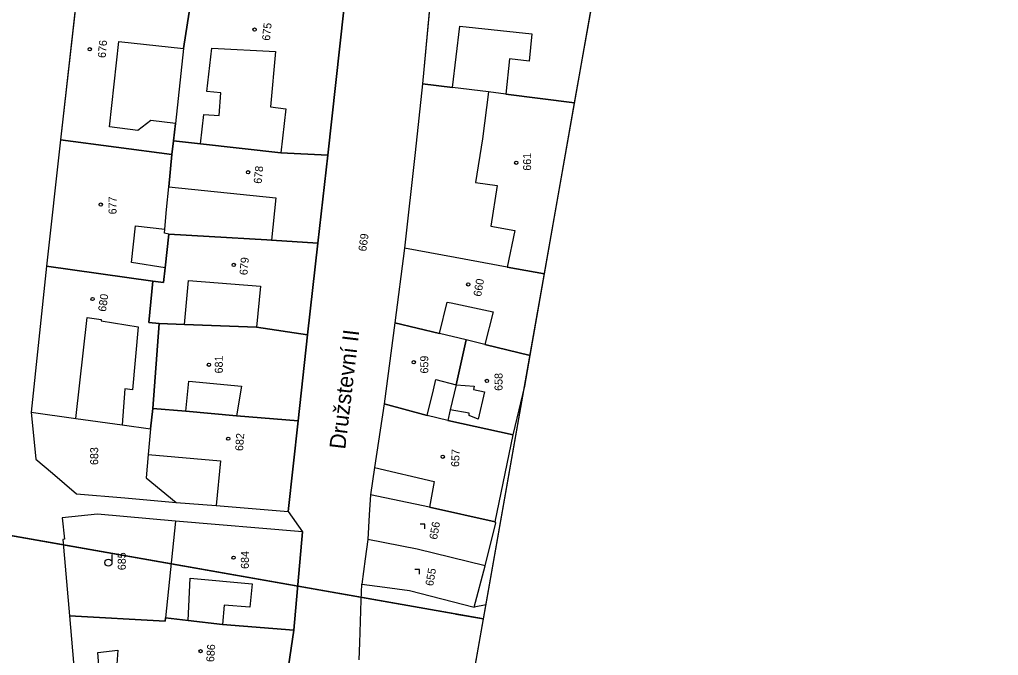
# Model space of a CAD drawing. Extents: x -534481 to -534256, y -1190577 to -1190138.
# Drawn here: x -534365.7 to -534261.7, y -1190477.6 to -1190410 of the extents above; entities that cross this region are included whole.
import ezdxf

# ---------------------------------------------------------------- set-up
doc = ezdxf.new("R2010")
doc.units = 0
for name, color, linetype in [('_rámeček', 7, 'Continuous'), ('_rámeček_mřížka', 7, 'Continuous'), ('Hranice parcel', 7, 'Continuous'), ('Parcelní čísla', 7, 'Continuous'), ('Polygon budovy', 7, 'Continuous'), ('Pop  PČ popisy', 7, 'Continuous'), ('Značky budov', 7, 'Continuous'), ('Značky kultur', 7, 'Continuous')]:
    doc.layers.add(name, color=color, linetype=linetype)

msp = doc.modelspace()

# ---------------------------------------------------------------- linework, layer by layer
at = {"layer": '_rámeček'}
for q in [(-534298.13, -1190370.27), (-534462.61, -1190447.89)]:
    msp.add_line((-534316.37, -1190473.68), q, dxfattribs=at)
for points in [[(-534407.91, -1190137.67), (-534480.84, -1190551.29), (-534334.6, -1190577.08), (-534261.67, -1190163.46)], [(-534298.13, -1190370.27), (-534444.38, -1190344.48), (-534462.61, -1190447.89), (-534316.37, -1190473.68)], [(-534480.84, -1190551.29), (-534334.6, -1190577.08), (-534316.37, -1190473.68)]]:
    msp.add_lwpolyline(points, dxfattribs=at)
at = {"layer": '_rámeček_mřížka'}
msp.add_line((-534319.32, -1190473.15), (-534316.37, -1190473.68), dxfattribs=at)
msp.add_lwpolyline([(-534480.84, -1190551.29), (-534334.6, -1190577.08), (-534261.67, -1190163.46)], dxfattribs=at)
at = {"layer": 'Hranice parcel'}
for p, q in [((-534321.81, -1190405.38), (-534322.86, -1190416.77)), ((-534359.48, -1190406.45), (-534361.32, -1190422.75)), ((-534331.23, -1190408.93), (-534332.91, -1190424.36)), ((-534361.32, -1190422.75), (-534362.8, -1190436.16)), ((-534361.32, -1190422.75), (-534349.49, -1190424.31)), ((-534349.49, -1190424.31), (-534349.31, -1190422.85)), ((-534332.91, -1190424.36), (-534333.96, -1190433.74)), ((-534333.96, -1190433.74), (-534335.08, -1190443.48)), ((-534324.75, -1190434.26), (-534325.81, -1190442.2)), ((-534362.8, -1190436.16), (-534364.44, -1190451.69)), ((-534362.8, -1190436.16), (-534351.49, -1190437.77)), ((-534351.49, -1190451.29), (-534350.82, -1190442.28)), ((-534325.81, -1190442.2), (-534326.91, -1190450.79)), ((-534335.08, -1190443.48), (-534336.06, -1190452.6)), ((-534313.23, -1190454.11), (-534312, -1190448.93)), ((-534351.77, -1190453.45), (-534351.49, -1190451.29)), ((-534336.06, -1190452.6), (-534337.13, -1190462.26)), ((-534313.23, -1190454.11), (-534320.15, -1190452.59)), ((-534351.77, -1190453.45), (-534351.99, -1190456.19)), ((-534315.15, -1190463.36), (-534313.23, -1190454.11)), ((-534337.13, -1190462.26), (-534335.61, -1190464.4)), ((-534349.11, -1190463.29), (-534350.15, -1190473.56)), ((-534335.61, -1190464.4), (-534349.11, -1190463.29)), ((-534335.61, -1190464.4), (-534336.54, -1190474.87)), ((-534317.36, -1190472.42), (-534316.19, -1190468.02)), ((-534360.35, -1190473.34), (-534359.92, -1190478.31))]:
    msp.add_line(p, q, dxfattribs=at)
for points in [[(-534347.45, -1190408.02), (-534348.24, -1190413.03), (-534349.11, -1190420.99), (-534349.31, -1190422.85)], [(-534322.86, -1190416.77), (-534323.65, -1190424.09), (-534324.75, -1190434.26)], [(-534306.7, -1190418.82), (-534314.01, -1190417.87), (-534315.84, -1190417.64), (-534319.66, -1190417.17), (-534322.86, -1190416.77)], [(-534349.31, -1190422.85), (-534346.43, -1190423.17), (-534337.91, -1190424.11), (-534332.91, -1190424.36)], [(-534349.79, -1190432.77), (-534350.28, -1190432.67), (-534350.24, -1190432.22), (-534350.04, -1190430.15), (-534349.82, -1190427.74), (-534349.49, -1190424.31)], [(-534351.49, -1190437.77), (-534350.38, -1190437.91), (-534350.2, -1190436.34), (-534349.79, -1190432.77)], [(-534349.79, -1190432.77), (-534345.53, -1190433.02), (-534339.38, -1190433.37), (-534338.88, -1190433.41), (-534333.96, -1190433.74)], [(-534309.9, -1190437), (-534313.86, -1190436.27), (-534319.38, -1190435.25), (-534324.75, -1190434.26)], [(-534351.49, -1190437.77), (-534351.94, -1190442.14), (-534350.82, -1190442.28)], [(-534350.82, -1190442.28), (-534348.14, -1190442.37), (-534340.49, -1190442.65), (-534335.08, -1190443.48)], [(-534318.21, -1190444.01), (-534321.04, -1190443.31), (-534325.81, -1190442.2)], [(-534318.21, -1190444.01), (-534319.29, -1190448.78), (-534319.9, -1190451.46), (-534320.15, -1190452.59)], [(-534311.43, -1190445.66), (-534316.23, -1190444.51), (-534318.21, -1190444.01)], [(-534326.91, -1190450.79), (-534327.94, -1190457.58), (-534328.38, -1190460.47)], [(-534320.15, -1190452.59), (-534322.37, -1190452.05), (-534326.91, -1190450.79)], [(-534364.44, -1190451.69), (-534363.92, -1190456.68), (-534362.18, -1190458.17), (-534359.62, -1190460.37), (-534354.49, -1190460.81), (-534349.01, -1190461.28)], [(-534364.44, -1190451.69), (-534359.68, -1190452.35), (-534354.78, -1190453.03), (-534351.77, -1190453.45)], [(-534351.49, -1190451.29), (-534348, -1190451.6), (-534342.6, -1190452.08), (-534336.06, -1190452.6)], [(-534351.99, -1190456.19), (-534352.2, -1190458.68), (-534349.01, -1190461.28)], [(-534349.01, -1190461.28), (-534344.78, -1190461.63), (-534337.13, -1190462.26)], [(-534328.38, -1190460.47), (-534328.51, -1190462.62), (-534328.68, -1190465.22)], [(-534315.15, -1190463.36), (-534322.12, -1190461.79), (-534328.38, -1190460.47)], [(-534349.11, -1190463.29), (-534357.38, -1190462.53), (-534361.12, -1190462.94), (-534360.89, -1190465.2), (-534361.07, -1190465.23), (-534360.35, -1190473.34)], [(-534316.19, -1190468.02), (-534315.05, -1190463.47), (-534315.15, -1190463.36)], [(-534328.68, -1190465.22), (-534328.95, -1190467.29), (-534329.3, -1190469.99)], [(-534316.19, -1190468.02), (-534323.42, -1190466.26), (-534328.68, -1190465.22)], [(-534329.58, -1190478.02), (-534329.52, -1190476.22), (-534329.36, -1190471.67), (-534329.3, -1190469.99)], [(-534329.3, -1190469.99), (-534326.86, -1190470.31), (-534324.23, -1190470.65), (-534317.36, -1190472.42)], [(-534316.1, -1190472.16), (-534317.36, -1190472.42)], [(-534360.35, -1190473.34), (-534350.19, -1190473.9), (-534350.15, -1190473.56)], [(-534350.15, -1190473.56), (-534347.75, -1190473.84), (-534344.1, -1190474.27), (-534336.54, -1190474.87)], [(-534336.54, -1190474.87), (-534337.79, -1190483.49), (-534339.53, -1190483.31)]]:
    msp.add_lwpolyline(points, dxfattribs=at)
at = {"layer": 'Polygon budovy'}
for p, q in [((-534306.7, -1190418.82), (-534304.95, -1190408.92)), ((-534309.9, -1190437), (-534306.7, -1190418.82)), ((-534311.43, -1190445.66), (-534309.9, -1190437)), ((-534312, -1190448.93), (-534311.43, -1190445.66))]:
    msp.add_line(p, q, dxfattribs=at)
for points in [[(-534304.95, -1190408.92), (-534304.7, -1190406.9), (-534310.69, -1190406.47), (-534319.12, -1190405.49), (-534321.81, -1190405.38), (-534322.86, -1190416.77), (-534319.66, -1190417.17), (-534318.89, -1190410.64), (-534311.23, -1190411.47), (-534311.53, -1190414.36), (-534313.6, -1190414.13), (-534314.01, -1190417.87), (-534306.7, -1190418.82)], [(-534306.7, -1190418.82), (-534314.01, -1190417.87), (-534315.84, -1190417.64), (-534316.47, -1190422.62), (-534317.22, -1190427.29), (-534314.94, -1190427.61), (-534315.59, -1190431.92), (-534313.05, -1190432.39), (-534313.86, -1190436.27), (-534309.9, -1190437)], [(-534309.9, -1190437), (-534313.86, -1190436.27), (-534319.38, -1190435.25), (-534324.75, -1190434.26), (-534325.81, -1190442.2), (-534321.04, -1190443.31), (-534320.22, -1190439.99), (-534319.82, -1190440.07), (-534315.33, -1190441.03), (-534316.23, -1190444.51), (-534311.43, -1190445.66)], [(-534311.43, -1190445.66), (-534316.23, -1190444.51), (-534318.21, -1190444.01), (-534319.29, -1190448.78), (-534317.38, -1190448.92), (-534317.43, -1190449.28), (-534316.26, -1190449.52), (-534316.94, -1190452.43), (-534317.91, -1190452.03), (-534317.88, -1190451.8), (-534319.9, -1190451.46), (-534320.15, -1190452.59), (-534313.23, -1190454.11), (-534312, -1190448.93)]]:
    msp.add_lwpolyline(points, dxfattribs=at)
for points in [[(-534350.73, -1190407.46), (-534351.28, -1190407.37), (-534359.48, -1190406.45), (-534361.32, -1190422.75), (-534349.49, -1190424.31), (-534349.31, -1190422.85), (-534349.11, -1190420.99), (-534351.71, -1190420.68), (-534353.09, -1190421.73), (-534356.12, -1190421.36), (-534355.1, -1190412.3), (-534348.24, -1190413.03), (-534347.45, -1190408.02)], [(-534349.31, -1190422.85), (-534346.43, -1190423.17), (-534346.07, -1190420.03), (-534344.47, -1190420.16), (-534344.27, -1190417.73), (-534345.78, -1190417.61), (-534345.25, -1190412.99), (-534338.47, -1190413.36), (-534338.99, -1190419.24), (-534337.36, -1190419.45), (-534337.91, -1190424.11), (-534332.91, -1190424.36), (-534331.23, -1190408.93), (-534336.56, -1190408.56), (-534340.34, -1190408.33), (-534347.45, -1190408.02), (-534348.24, -1190413.03), (-534349.11, -1190420.99)], [(-534353.76, -1190435.78), (-534353.33, -1190431.87), (-534350.24, -1190432.22), (-534350.04, -1190430.15), (-534349.82, -1190427.74), (-534349.49, -1190424.31), (-534361.32, -1190422.75), (-534362.8, -1190436.16), (-534351.49, -1190437.77), (-534350.38, -1190437.91), (-534350.2, -1190436.34)], [(-534349.82, -1190427.74), (-534338.42, -1190428.92), (-534338.88, -1190433.41), (-534333.96, -1190433.74), (-534332.91, -1190424.36), (-534337.91, -1190424.11), (-534346.43, -1190423.17), (-534349.31, -1190422.85), (-534349.49, -1190424.31)], [(-534338.88, -1190433.41), (-534339.38, -1190433.37), (-534345.53, -1190433.02), (-534349.79, -1190432.77), (-534350.2, -1190436.34), (-534350.38, -1190437.91), (-534351.49, -1190437.77), (-534351.94, -1190442.14), (-534350.82, -1190442.28), (-534348.14, -1190442.37), (-534347.71, -1190437.68), (-534340.05, -1190438.3), (-534340.49, -1190442.65), (-534335.08, -1190443.48), (-534333.96, -1190433.74)], [(-534356.98, -1190441.98), (-534353.08, -1190442.61), (-534353.66, -1190449.31), (-534354.47, -1190449.22), (-534354.78, -1190453.03), (-534351.77, -1190453.45), (-534351.49, -1190451.29), (-534350.82, -1190442.28), (-534351.94, -1190442.14), (-534351.49, -1190437.77), (-534362.8, -1190436.16), (-534364.44, -1190451.69), (-534359.68, -1190452.35), (-534358.48, -1190441.61), (-534356.98, -1190441.84)], [(-534348.14, -1190442.37), (-534350.82, -1190442.28), (-534351.49, -1190451.29), (-534348, -1190451.6), (-534347.67, -1190448.41), (-534342.08, -1190448.94), (-534342.6, -1190452.08), (-534336.06, -1190452.6), (-534335.08, -1190443.48), (-534340.49, -1190442.65)], [(-534326.91, -1190450.79), (-534322.37, -1190452.05), (-534321.7, -1190449.32), (-534321.43, -1190448.22), (-534319.29, -1190448.78), (-534318.21, -1190444.01), (-534321.04, -1190443.31), (-534325.81, -1190442.2)], [(-534327.94, -1190457.58), (-534321.62, -1190459.05), (-534322.12, -1190461.79), (-534315.15, -1190463.36), (-534313.23, -1190454.11), (-534320.15, -1190452.59), (-534322.37, -1190452.05), (-534326.91, -1190450.79)], [(-534344.78, -1190461.63), (-534337.13, -1190462.26), (-534336.06, -1190452.6), (-534342.6, -1190452.08), (-534348, -1190451.6), (-534351.49, -1190451.29), (-534351.77, -1190453.45), (-534351.99, -1190456.19), (-534344.31, -1190456.87)], [(-534341.2, -1190472.43), (-534343.94, -1190472.2), (-534344.1, -1190474.27), (-534336.54, -1190474.87), (-534335.61, -1190464.4), (-534349.11, -1190463.29), (-534350.15, -1190473.56), (-534347.75, -1190473.84), (-534347.55, -1190469.33), (-534340.96, -1190469.95)], [(-534360.35, -1190473.34), (-534359.92, -1190478.31), (-534359.56, -1190481.78), (-534357.01, -1190481.97), (-534357.36, -1190477.25), (-534355.22, -1190476.99), (-534355.37, -1190478.98), (-534346.45, -1190479.65), (-534346.59, -1190482.73), (-534339.53, -1190483.31), (-534337.79, -1190483.49), (-534336.54, -1190474.87), (-534344.1, -1190474.27), (-534347.75, -1190473.84), (-534350.15, -1190473.56), (-534350.19, -1190473.9)]]:
    msp.add_lwpolyline(points, close=True, dxfattribs=at)
at = {"layer": 'Značky budov'}
for centre in [(-534340.69, -1190411.01), (-534358.2, -1190413.1), (-534312.9, -1190425.18), (-534341.39, -1190426.18), (-534357.04, -1190429.62), (-534342.9, -1190436.03), (-534318, -1190438.11), (-534357.91, -1190439.66), (-534345.55, -1190446.65), (-534323.79, -1190446.38), (-534316.01, -1190448.37), (-534343.5, -1190454.51), (-534320.7, -1190456.43), (-534342.92, -1190467.16), (-534346.44, -1190477.1)]:
    msp.add_circle(centre, 0.175, dxfattribs=at)
at = {"layer": 'Značky kultur'}
for p, q in [((-534322.59, -1190463.61), (-534323.09, -1190463.61)), ((-534322.59, -1190464.11), (-534322.59, -1190463.61)), ((-534355.84, -1190467.69), (-534355.84, -1190466.81)), ((-534323.17, -1190468.43), (-534323.67, -1190468.43)), ((-534323.17, -1190468.93), (-534323.17, -1190468.43))]:
    msp.add_line(p, q, dxfattribs=at)
msp.add_circle((-534356.22, -1190467.69), 0.375, dxfattribs=at)

# ---------------------------------------------------------------- texts
at = {"layer": 'Parcelní čísla'}
for s, rotation, p in [('675', 84, (-534339.07, -1190412.23)), ('676', 85, (-534356.52, -1190414.06)), ('661', 90, (-534311.32, -1190426.02)), ('678', 84, (-534339.96, -1190427.44)), ('677', 90, (-534355.36, -1190430.66)), ('669', 82, (-534328.84, -1190434.64)), ('679', 85, (-534341.46, -1190437.15)), ('660', 80, (-534316.63, -1190439.45)), ('680', 82, (-534356.49, -1190441.05)), ('681', 90, (-534344.07, -1190447.57)), ('659', 90, (-534322.24, -1190447.58)), ('658', 90, (-534314.35, -1190449.42)), ('682', 86, (-534341.92, -1190455.84)), ('683', 90, (-534357.31, -1190457.31)), ('657', 88, (-534318.97, -1190457.53)), ('656', 80, (-534321.31, -1190465.28)), ('685', 90, (-534354.38, -1190468.49)), ('684', 90, (-534341.3, -1190468.35)), ('655', 80, (-534321.73, -1190470.22)), ('686', 86, (-534345, -1190478.28))]:
    msp.add_text(s, height=0.85, rotation=rotation, dxfattribs=at).set_placement(p)
at = {"layer": 'Pop  PČ popisy'}
msp.add_text('Družstevní II', height=1.7, rotation=83.2137, dxfattribs=at).set_placement((-534331.07, -1190455.69))

doc.saveas('drawing.dxf')
